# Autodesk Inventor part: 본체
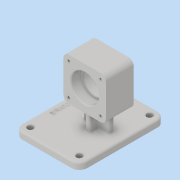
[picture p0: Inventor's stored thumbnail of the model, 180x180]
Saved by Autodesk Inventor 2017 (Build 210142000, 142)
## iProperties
Part Number: 본체
Material: 일반
Document SubType Name: Modeling
Designer: 7-1
Density: 1 g/cm^3
Appearance: 기본값
Author: 7-1
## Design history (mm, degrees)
sketch "스케치1"
  geometry: L1 (-32, -32)-(32, -32); L2 (32, -32)-(32, 32); L3 (32, 32)-(-32, 32); L4 (-32, 32)-(-32, -32); L5 (-32, -32)-(32, 32); L6 (32, -32)-(-32, 32); 1 further point
  constraints: 12 end point, 2 midpoint, 2 parallel, 1 horizontal, 1 perpendicular
  dimensions: "d0" = 64 distance of L3.end L2.end; "d1" = 64 distance of L2.end L1.end
extrude "돌출1" new body sketch "스케치1" distance "d2" = 21; taper "d3" = 0 deg
sketch "스케치3"
  geometry: 2 further points
  constraints: 1 coincident
hole "구멍1" sketch "스케치3" at (0, 0) diameter "d5" = 36; stored, may be unused: countersink angle "d9" = 90 deg, drill point angle "d11" = 0 deg; dims "d6" = 6, "d7" = 42, "d8" = 15, "d10" = 8
fillet "모깎기1" dims "d12" = 8
hole "구멍2" diameter "d15" = 3.242; stored, may be unused: countersink angle "d19" = 90 deg, drill point angle "d21" = 118 deg; dims "d13" = 10, "d14" = 10, "d16" = 8, "d17" = 42, "d18" = 15, "d20" = 10
hole "구멍3" diameter "d24" = 3.242; stored, may be unused: countersink angle "d28" = 90 deg, drill point angle "d30" = 118 deg; dims "d22" = 10, "d23" = 10, "d25" = 8, "d26" = 42, "d27" = 15, "d29" = 10
hole "구멍4" diameter "d34" = 3.242; stored, may be unused: countersink angle "d38" = 90 deg, drill point angle "d40" = 118 deg; dims "d32" = 10, "d33" = 10, "d35" = 8, "d36" = 42, "d37" = 15, "d39" = 10
hole "구멍5" diameter "d43" = 3.242; stored, may be unused: countersink angle "d47" = 90 deg, drill point angle "d49" = 118 deg; dims "d41" = 10, "d42" = 10, "d44" = 8, "d45" = 42, "d46" = 15, "d48" = 10
fillet "모깎기2" dims "d50" = 0.3
chamfer "모따기1" distance "d51" = 1; stored, may be unused: second distance "d52" = 2, angle "d53" = 45 deg
sketch "스케치5"
  geometry: L1 (-36, -60)-(62, -60); L2 (62, -60)-(62, -70); L3 (62, -70)-(-36, -70); L4 (-36, -70)-(-36, -60); 1 further point
  constraints: 8 end point, 2 parallel, 1 horizontal, 1 perpendicular
  dimensions: "d54" = 10 distance of L3.end L1.start; "d55" = 70 distance from line of L3 point (0, 0); "d56" = 98 distance of L2.end L3.end; "d57" = 62 distance from line of point (0, 0) L2
extrude "돌출2" join sketch "스케치5" distance "d58" = 65; taper "d59" = 0 deg
fillet "모깎기3" dims "d60" = 12
hole "구멍6" diameter "d63" = 9; stored, may be unused: countersink angle "d67" = 90 deg, drill point angle "d69" = 0 deg; dims "d61" = 10, "d62" = 10, "d64" = 9, "d65" = 42, "d66" = 15, "d68" = 10
hole "구멍7" diameter "d72" = 9; stored, may be unused: countersink angle "d76" = 90 deg, drill point angle "d78" = 0 deg; dims "d70" = 10, "d71" = 10, "d73" = 9, "d74" = 42, "d75" = 15, "d77" = 10
sketch "스케치6"
  geometry: L1 (54, 48)-(46, 48); L2 (46, 48)-(46, 82); L3 (46, 82)-(54, 82); L4 (54, 82)-(54, 48); L5 (54, 48)-(46, 82); L6 (46, 48)-(54, 82); L7 (70, 61)-(30, 61); L8 (30, 61)-(30, 69); L9 (30, 69)-(70, 69); L10 (70, 69)-(70, 61); L11 (70, 61)-(30, 69); L12 (30, 61)-(70, 69); 1 further point
  constraints: 24 end point, 4 midpoint, 4 parallel, 2 horizontal, 2 perpendicular
  dimensions: "d79" = 8 distance of L2.end L3.end; "d80" = 34 distance of L1.end L2.end; "d81" = 40 distance of L8.end L9.end; "d82" = 8 distance of L7.end L8.end
extrude "돌출3" join sketch "스케치6" stored distance "d83" = 65; taper "d84" = 0 deg
fillet "모깎기4" dims "d85" = 3
fillet "모깎기5" dims "d86" = 3
fillet "모깎기6" dims "d87" = 3
node "작업 평면1"
sketch "스케치7"
  geometry: L1 (-12, 115)-(-12, 9) reference; 2 further points
  constraints: 1 horizontal alignment, 1 other
  dimensions: "d89" = 10 distance from line of point (-2, 62) L1
feature "엠보싱1" sketch "스케치7" dims "d0" = 64, "d1" = 64, "d25" = 8, "d90" = 0.5, "d91" = 0
node "솔리드1"
mirror "미러1"
other parameters: "d88" = 16.75
